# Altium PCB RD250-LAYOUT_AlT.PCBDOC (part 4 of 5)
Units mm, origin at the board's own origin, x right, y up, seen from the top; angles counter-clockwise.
Board outline 318.5 x 135 mm, 6 copper layers (TOP, Mid-Layer 1, Mid-Layer 2, Mid-Layer 3, Mid-Layer 4, BOTTOM), stack 1.422 mm thick; 550 components, 251 nets, 1350 pads, 626 vias.
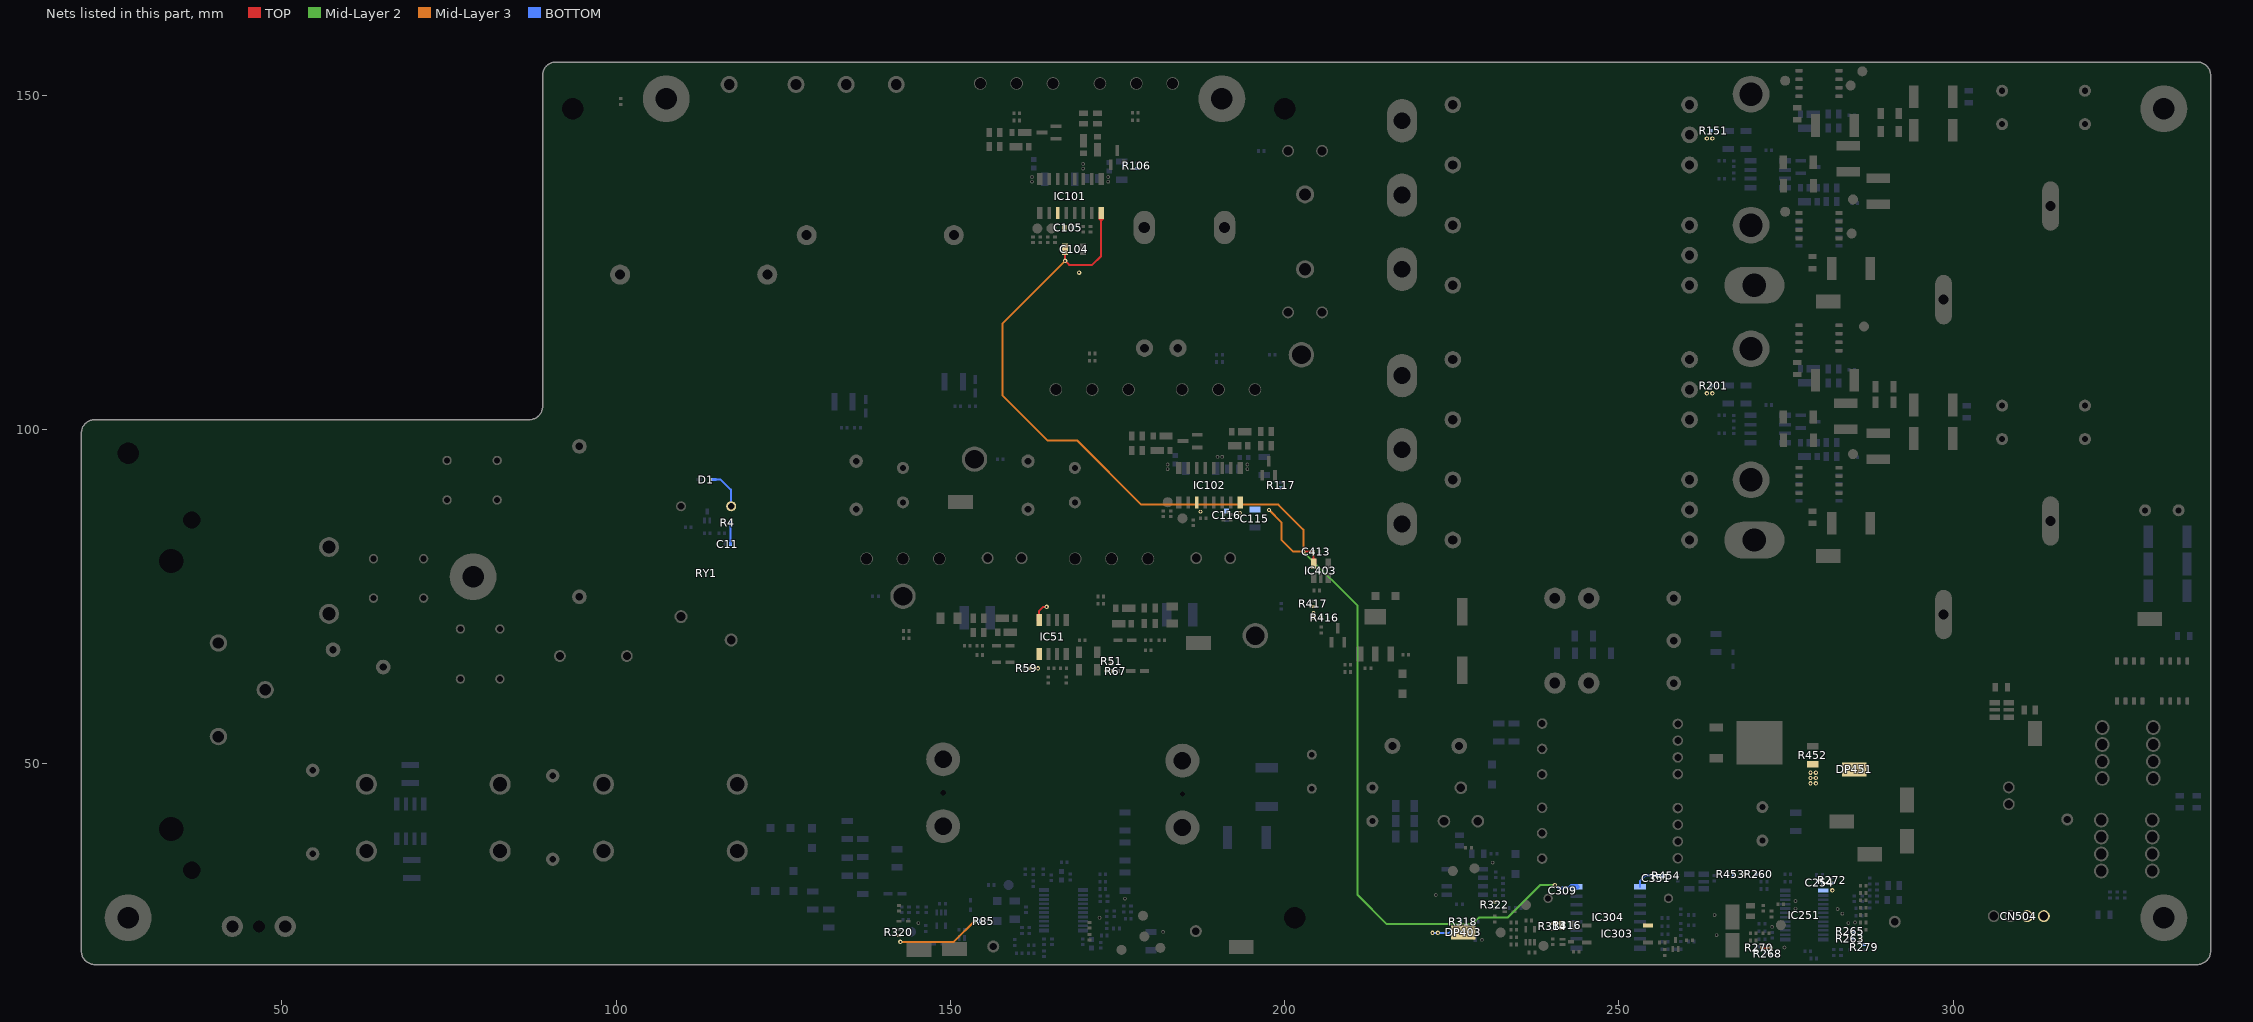
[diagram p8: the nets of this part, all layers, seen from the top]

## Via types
v1: diameter 0.65, hole 0.3, TOP to BOTTOM, 626 vias

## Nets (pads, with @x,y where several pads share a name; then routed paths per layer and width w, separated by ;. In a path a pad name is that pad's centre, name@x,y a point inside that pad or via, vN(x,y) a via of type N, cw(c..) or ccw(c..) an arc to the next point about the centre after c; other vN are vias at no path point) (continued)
VCC5R0_1: C104.2 C105.2 C115.2 C116.2 C309.2 C413.2 IC101.3 IC101.8 IC102.3 IC102.8 IC304.16 IC403.5 pad.@187.4,87.75 pad.@193.3,87.55 | length 199.5
  TOP w0.3: C104.2@167.15,126.61 v1(167.15,125.25) 167.75,124.65 171.2,124.65 172.533,125.983 IC101.8@172.533,131.659 ; v1(202.8,81.75) C413.2@204.147,81.75 ; IC403.5@204.312,80.386 C413.2@204.312,81.569
  TOP w0.425: C413.2@204.312,81.569 C413.2@204.312,81.75
  TOP w0.45: C413.2@204.147,81.75 204.312,81.75 C413.2@204.325,81.75
  TOP w0.824: IC101.8@172.533,131.659 IC101.8@172.533,132.392
  TOP w0.825: IC403.5@204.312,79.975 IC403.5@204.312,80.386
  TOP w0.92: C104.2@167.15,126.61 C104.2@167.15,127
  Mid-Layer 2 w0.3: v1(202.8,81.75) 210.9,73.65 210.9,30.4 215.25,26.05 228.1,26.05 229.042,26.992 cw(c229.183,26.85) 229.183,27.05 233.4,27.05 238.25,31.9 v1(240.4,31.9)
  Mid-Layer 3 w0.3: v1(167.15,125.25) 157.75,115.85 157.75,105.15 164.55,98.35 169,98.35 178.55,88.8 199.05,88.8 202.8,85.05 v1(202.8,81.75) 201.3,81.75 199.5,83.55 199.5,86.15 v1(197.65,88)
  BOTTOM w0.3: v1(240.4,31.9) 240.825,31.475 C309.2@241.372,31.475 ; C309.2@241.55,31.475 242.143,31.475 242.3,31.632 IC304.16@242.96,31.632
  BOTTOM w0.45: C309.2@241.372,31.475 C309.2@241.55,31.475
  BOTTOM w0.825: IC304.16@242.96,31.632 IC304.16@243.68,31.632
VCC5R0_2: C351.2 IC304.1 R454.2 | length 4.7
  BOTTOM w0.3: IC304.1@253.12,31.632 253.12,32.47 253.95,33.3 C351.2@255.431,33.3 ; C351.2@255.769,33.3 R454.2@256.497,33.3
  BOTTOM w0.4: C351.2@255.431,33.3 C351.2@255.769,33.3
  BOTTOM w0.45: R454.2@256.497,33.3 R454.2@256.675,33.3
VCC12R0_1: C11.2 D1.C DP403.1 IC51.1 IC51.8 R4.1 R51.1 R59.2 R67.2 R85.1 R106.1 R117.1 R314.2 R316.2 R318.2 R320.2 R322.2 R416.1 R417.1 RY1.4 | length 31.7
  TOP w0.3: R59.2@162.003,64.3 v1(163.1,64.3) ; IC51.8@163.257,72.043 163.257,72.907 163.85,73.5 v1(164.4,73.5) ; R314.2@240.278,26.125 R316.2@241.168,26.125
  TOP w0.45: R59.2@161.825,64.3 R59.2@162.003,64.3 ; R314.2@240.1,26.125 R314.2@240.278,26.125
  TOP w0.53: R316.2@241.168,26.125 R316.2@241.6,26.125
  TOP w0.825: IC51.8@163.257,71.557 IC51.8@163.257,72.043
  Mid-Layer 3 w0.3: v1(142.5,23.4) 150.417,23.4 ccw(c150.417,23.6) 150.559,23.459 v1(153.6,26.5)
  BOTTOM w0.3: D1.C@114.887,92.55 115.529,92.55 cw(c115.529,92.35) 115.671,92.491 117.141,91.021 cw(c117,90.879) 117.2,90.879 RY1.4@117.2,88.55 ; C11.2@117.125,83.087 R4.1@117.125,85.913 ; v1(222.1,24.75) v1(222.9,24.75) 224.625,24.75 R318.2@226.275,26.4
  BOTTOM w0.4: D1.C@114.5,92.55 D1.C@114.887,92.55
  BOTTOM w0.45: C11.2@117.125,82.9 C11.2@117.125,83.087 ; R4.1@117.125,85.913 R4.1@117.125,86.1
  other v1: 173.3,63.9 204.3,71.85 204.3,72.55 169.25,123.5
VCC12R0_2: CN504.1 CN504.2 DP451.1 IC303.6 pad.@268.8,33.5 R151.1 R201.1 R260.1 R452.2 R453.1
  other v1: 278.65,47.1 279.45,47.1 278.65,47.9 279.45,47.9 278.65,48.7 279.45,48.7 263.15,105.45 263.95,105.45 263.15,143.55 263.95,143.55
VREF_PSFB: C254.2 IC251.1 R263.2 R265.2 R268.2 R270.2 R272.2 R279.2 | length 1.3
  TOP w0.3: R270.2@271.553,22.5 v1(272.7,22.5)
  TOP w0.45: R270.2@271.375,22.5 R270.2@271.553,22.5
  other v1: 286.1,23.85 281.9,31.1
pads on no net: C51. C52. cam1. cam4. cam6. cam9. cam10. cam12. CN1. CN2.2 CN102.1 CN105.1 D104.NC D107.NC D113.NC D116.NC D405.NC IC1.1 IC1.4 IC1.5 IC1.8 IC101.7 IC101.12 IC101.13 IC102.7 IC102.12 IC102.13 IC151.1 IC151.8 IC201.1 IC201.8 IC251.16 IC304.7 IC304.10 IC403.4 IC451.4 T101.4 T101.6 T101.7 T151.1 T151.3 T151.4 T151.6 T151.7 T151.8 T151.9 T151.10 T151.11 T151.12 T201.1 T201.3 T201.4 T201.6 T201.7 T201.8 T201.9 T201.10 T201.11 T201.12 T401.2 T401.7 T401.10 T401.11 T401.14

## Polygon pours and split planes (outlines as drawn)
no net on Top Overlay "TOPOVERLAY378" (solid, pour order 0): 281.96,71.505 282.325,72.709 282.827,72.709 283.192,71.505 282.839,71.505 282.774,71.728 282.378,71.728 282.313,71.505
no net on Top Overlay "TOPOVERLAY377" (solid, pour order 0): 119 vertices, not listed, extent 280.833,71.505 281.873,72.709
no net on Top Overlay "TOPOVERLAY376" (solid, pour order 0): 145 vertices, not listed, extent 276.2,71.483 277.341,72.73
SIG1 on TOP "TOP127" (solid, pour order 372): 29 vertices, not listed, extent 52.1,45.209 64.395,74.2
VCC12R0_1 on TOP "TOP126" (solid, pour order 371): 142.1,22.9 cw(c142.1,23.05) 141.95,23.05 141.95,24.45 cw(c142.1,24.45) 142.1,24.6 142.65,24.6 cw(c142.65,24.45) 142.8,24.45 142.8,23.05 cw(c142.65,23.05) 142.65,22.9
SIG007123 on TOP "TOP125" (solid, pour order 370): 143.5,25.9 cw(c143.5,26.05) 143.35,26.05 143.35,26.55 cw(c143.5,26.55) 143.5,26.7 145.35,26.7 cw(c145.35,26.55) 145.5,26.55 145.5,26.05 cw(c145.35,26.05) 145.35,25.9
VCC12R0_1 on TOP "TOP124" (solid, pour order 369): 50 vertices, not listed, extent 226.248,24.348 240.325,30.7
SIG007124 on TOP "TOP123" (solid, pour order 368): 21 vertices, not listed, extent 237.15,24.785 240.324,25.75
SIG007127 on TOP "TOP122" (solid, pour order 367): 17 vertices, not listed, extent 231.15,27 233.05,28.7
SIG00797 on TOP "TOP121" (solid, pour order 366): 22 vertices, not listed, extent 234.2,24.8 236.85,29.65
SIG007112 on TOP "TOP120" (solid, pour order 365): 30 vertices, not listed, extent 229.284,20.75 239.45,23.916
PN on TOP "TOP119" (solid, pour order 364): 239.95,20.5 cw(c239.95,20.65) 239.8,20.65 239.8,23.05 cw(c239.95,23.05) 239.95,23.2 241.888,23.2 cw(c241.888,23.05) 241.994,23.156 242.95,22.2 243.25,22.2 cw(c243.25,22.05) 243.4,22.05 243.4,20.65 cw(c243.25,20.65) 243.25,20.5
SIG00234 on TOP "TOP118" (solid, pour order 363): 31 vertices, not listed, extent 149.985,22.263 165.964,27.37
SIG00233 on TOP "TOP117" (solid, pour order 362): 31 vertices, not listed, extent 144.954,21.854 165.964,30.17
SIG00839 on TOP "TOP116" (solid, pour order 361): 53 vertices, not listed, extent 207.676,65.977 214.675,75.748
SIG00839 on TOP "TOP115" (solid, pour order 360): 23 vertices, not listed, extent 212.684,64.109 214.05,66.973
SIGN267 on TOP "TOP114" (solid, pour order 359): 24 vertices, not listed, extent 143.601,69.675 149.11,72.383
SIG00447 on TOP "TOP113" (solid, pour order 358): 24 vertices, not listed, extent 266.25,127.1 281.2,137.5
SIG115 on TOP "TOP112" (solid, pour order 357): 24 vertices, not listed, extent 266.25,89 281.2,99.4
SIGN267 on TOP "TOP111" (solid, pour order 356): 36 vertices, not listed, extent 147.51,80.971 152.295,88.722
SIGN266 on TOP "TOP110" (solid, pour order 355): 51 vertices, not listed, extent 172.701,67.054 188.15,81.359
SIG199 on TOP "TOP109" (solid, pour order 354): 27 vertices, not listed, extent 80.144,44.471 100.612,62.805
SIG200 on TOP "TOP108" (solid, pour order 353): 80.875,35.202 cw(c82.643,36.97) 84.411,38.738 84.899,38.25 95.857,38.25 96.345,38.738 cw(c98.113,36.97) 99.881,35.202 98.661,33.982 cw(c96.893,35.75) 96.893,33.25 83.863,33.25 cw(c83.863,35.75) 82.095,33.982
VCC12R0_1 on TOP "TOP107" (solid, pour order 352): 32 vertices, not listed, extent 221.986,23.75 227.746,25.85
LGND on TOP "TOP106" (solid, pour order 351): 286.85,24.9 cw(c286.85,25.05) 286.7,25.05 286.7,31.95 cw(c286.85,31.95) 286.85,32.1 287.759,32.1 cw(c287.759,31.95) 287.9,32 292.497,27.403 cw(c292.391,27.297) 292.541,27.297 292.541,25.548 cw(c292.391,25.548) 292.497,25.442 291.999,24.944 cw(c291.893,25.05) 291.893,24.9
PFC_OUT on TOP "TOP105" (solid, pour order 350): 190.74,79.35 cw(c190.74,79.5) 190.59,79.5 190.59,81.7 cw(c190.74,81.7) 190.74,81.85 192.94,81.85 cw(c192.94,81.7) 193.09,81.7 193.09,79.5 cw(c192.94,79.5) 192.94,79.35
PFC_OUT on TOP "TOP104" (solid, pour order 349): 159.54,79.35 cw(c159.54,79.5) 159.39,79.5 159.39,81.7 cw(c159.54,81.7) 159.54,81.85 161.74,81.85 cw(c161.74,81.7) 161.89,81.7 161.89,79.5 cw(c161.74,79.5) 161.74,79.35
SIG11 on TOP "TOP103" (solid, pour order 348): 185.66,79.35 cw(c185.66,79.5) 185.51,79.5 185.51,81.7 cw(c185.66,81.7) 185.66,81.85 187.86,81.85 cw(c187.86,81.7) 188.01,81.7 188.01,79.5 cw(c187.86,79.5) 187.86,79.35
SIG12 on TOP "TOP102" (solid, pour order 347): 154.46,79.35 cw(c154.46,79.5) 154.31,79.5 154.31,81.7 cw(c154.46,81.7) 154.46,81.85 156.66,81.85 cw(c156.66,81.7) 156.81,81.7 156.81,79.5 cw(c156.66,79.5) 156.66,79.35
PN on TOP "TOP101" (solid, pour order 346): 167.56,79.35 cw(c167.56,79.5) 167.41,79.5 167.41,81.7 cw(c167.56,81.7) 167.56,81.85 169.76,81.85 cw(c169.76,81.7) 169.91,81.7 169.91,79.5 cw(c169.76,79.5) 169.76,79.35
PN on TOP "TOP100" (solid, pour order 345): 136.35,79.35 cw(c136.35,79.5) 136.2,79.5 136.2,81.7 cw(c136.35,81.7) 136.35,81.85 138.55,81.85 cw(c138.55,81.7) 138.7,81.7 138.7,79.5 cw(c138.55,79.5) 138.55,79.35
SIG22 on TOP "TOP99" (solid, pour order 344): 141.79,79.35 cw(c141.79,79.5) 141.64,79.5 141.64,81.7 cw(c141.79,81.7) 141.79,81.85 143.99,81.85 cw(c143.99,81.7) 144.14,81.7 144.14,79.5 cw(c143.99,79.5) 143.99,79.35
PN on TOP "TOP98" (solid, pour order 343): 140.7,150.15 cw(c140.7,150.3) 140.55,150.3 140.55,153 cw(c140.7,153) 140.7,153.15 143.1,153.15 cw(c143.1,153) 143.25,153 143.25,150.3 cw(c143.1,150.3) 143.1,150.15
PN on TOP "TOP97" (solid, pour order 342): 21 vertices, not listed, extent 230.6,21.5 236.9,26.6
SIG6 on TOP "TOP96" (solid, pour order 341): 42 vertices, not listed, extent 90.1,34.47 136.7,154.146
SIG0012 on TOP "TOP95" (solid, pour order 340): 26 vertices, not listed, extent 98.303,45.275 119.845,69.532
SIG2 on TOP "TOP94" (solid, pour order 339): 23 vertices, not listed, extent 38,34.032 64.2,55.8
SIGN266 on TOP "TOP93" (solid, pour order 338): 178.44,79.35 cw(c178.44,79.5) 178.29,79.5 178.29,81.7 cw(c178.44,81.7) 178.44,81.85 180.64,81.85 cw(c180.64,81.7) 180.79,81.7 180.79,79.5 cw(c180.64,79.5) 180.64,79.35
SIG18 on TOP "TOP92" (solid, pour order 337): 173,79.35 cw(c173,79.5) 172.85,79.5 172.85,81.7 cw(c173,81.7) 173,81.85 175.2,81.85 cw(c175.2,81.7) 175.35,81.7 175.35,79.5 cw(c175.2,79.5) 175.2,79.35
CONN004 on TOP "TOP91" (solid, pour order 336): 297.95,97 cw(c297.95,97.15) 297.8,97.15 297.8,105.3 cw(c297.95,105.3) 297.95,105.45 300.7,105.45 cw(c300.7,105.3) 300.85,105.3 300.85,97.15 cw(c300.7,97.15) 300.7,97
CONN004 on TOP "TOP90" (solid, pour order 335): 298,143.1 cw(c298,143.25) 297.85,143.25 297.85,151.4 cw(c298,151.4) 298,151.55 300.7,151.55 cw(c300.7,151.4) 300.85,151.4 300.85,143.25 cw(c300.7,143.25) 300.7,143.1
LGND on TOP "TOP89" (solid, pour order 334): 110 vertices, not listed, extent 282.15,69.825 337.9,154.45
SIG00852 on TOP "TOP88" (solid, pour order 333): 23 vertices, not listed, extent 267.6,41.8 279.9,60.4
SIG00345 on TOP "TOP87" (solid, pour order 332): 182.25,93.35 cw(c182.25,93.5) 182.1,93.5 182.1,95 cw(c182.25,95) 182.25,95.15 184.45,95.15 cw(c184.45,95) 184.6,95 184.6,93.5 cw(c184.45,93.5) 184.45,93.35
SIG00858 on TOP "TOP86" (solid, pour order 331): 30 vertices, not listed, extent 204.166,74 206.9,78.236
CONN002 on TOP "TOP85" (solid, pour order 330): 164.66,104.85 cw(c164.66,105) 164.51,105 164.51,107.2 cw(c164.66,107.2) 164.66,107.35 166.86,107.35 cw(c166.86,107.2) 167.01,107.2 167.01,105 cw(c166.86,105) 166.86,104.85
SIG00343 on TOP "TOP84" (solid, pour order 329): 170.1,104.85 cw(c170.1,105) 169.95,105 169.95,107.2 cw(c170.1,107.2) 170.1,107.35 172.3,107.35 cw(c172.3,107.2) 172.45,107.2 172.45,105 cw(c172.3,105) 172.3,104.85
SIG00351 on TOP "TOP83" (solid, pour order 328): 175.54,104.85 cw(c175.54,105) 175.39,105 175.39,107.2 cw(c175.54,107.2) 175.54,107.35 177.74,107.35 cw(c177.74,107.2) 177.89,107.2 177.89,105 cw(c177.74,105) 177.74,104.85
SIG00352 on TOP "TOP82" (solid, pour order 327): 194.44,104.85 cw(c194.44,105) 194.29,105 194.29,107.2 cw(c194.44,107.2) 194.44,107.35 196.64,107.35 cw(c196.64,107.2) 196.79,107.2 196.79,105 cw(c196.64,105) 196.64,104.85
CONN002 on TOP "TOP81" (solid, pour order 326): 189,104.85 cw(c189,105) 188.85,105 188.85,107.2 cw(c189,107.2) 189,107.35 191.2,107.35 cw(c191.2,107.2) 191.35,107.2 191.35,105 cw(c191.2,105) 191.2,104.85
PN on TOP "TOP80" (solid, pour order 325): 183.56,104.85 cw(c183.56,105) 183.41,105 183.41,107.2 cw(c183.56,107.2) 183.56,107.35 185.76,107.35 cw(c185.76,107.2) 185.91,107.2 185.91,105 cw(c185.76,105) 185.76,104.85
SIG8 on TOP "TOP79" (solid, pour order 324): 125.7,150.15 cw(c125.7,150.3) 125.55,150.3 125.55,153 cw(c125.7,153) 125.7,153.15 128.1,153.15 cw(c128.1,153) 128.25,153 128.25,150.3 cw(c128.1,150.3) 128.1,150.15
PFC_OUT on TOP "TOP78" (solid, pour order 323): 115.7,150.15 cw(c115.7,150.3) 115.55,150.3 115.55,153 cw(c115.7,153) 115.7,153.15 118.1,153.15 cw(c118.1,153) 118.25,153 118.25,150.3 cw(c118.1,150.3) 118.1,150.15
SIGN267 on TOP "TOP77" (solid, pour order 322): 147.24,79.35 cw(c147.24,79.5) 147.09,79.5 147.09,81.7 cw(c147.24,81.7) 147.24,81.85 149.44,81.85 cw(c149.44,81.7) 149.59,81.7 149.59,79.5 cw(c149.44,79.5) 149.44,79.35
SIG00343 on TOP "TOP76" (solid, pour order 321): 158.8,150.55 cw(c158.8,150.7) 158.65,150.7 158.65,152.9 cw(c158.8,152.9) 158.8,153.05 161,153.05 cw(c161,152.9) 161.15,152.9 161.15,150.7 cw(c161,150.7) 161,150.55
SIG00356 on TOP "TOP75" (solid, pour order 320): 153.36,150.55 cw(c153.36,150.7) 153.21,150.7 153.21,152.9 cw(c153.36,152.9) 153.36,153.05 155.56,153.05 cw(c155.56,152.9) 155.71,152.9 155.71,150.7 cw(c155.56,150.7) 155.56,150.55
PN on TOP "TOP74" (solid, pour order 319): 182.14,150.55 cw(c182.14,150.7) 181.99,150.7 181.99,152.9 cw(c182.14,152.9) 182.14,153.05 184.34,153.05 cw(c184.34,152.9) 184.49,152.9 184.49,150.7 cw(c184.34,150.7) 184.34,150.55
SIG00362 on TOP "TOP73" (solid, pour order 318): 176.7,150.55 cw(c176.7,150.7) 176.55,150.7 176.55,152.9 cw(c176.7,152.9) 176.7,153.05 178.9,153.05 cw(c178.9,152.9) 179.05,152.9 179.05,150.7 cw(c178.9,150.7) 178.9,150.55
SIG00342 on TOP "TOP72" (solid, pour order 317): 171.26,150.55 cw(c171.26,150.7) 171.11,150.7 171.11,152.9 cw(c171.26,152.9) 171.26,153.05 173.46,153.05 cw(c173.46,152.9) 173.61,152.9 173.61,150.7 cw(c173.46,150.7) 173.46,150.55
SIG00362 on TOP "TOP71" (solid, pour order 316): 164.24,150.55 cw(c164.24,150.7) 164.09,150.7 164.09,152.9 cw(c164.24,152.9) 164.24,153.05 166.44,153.05 cw(c166.44,152.9) 166.59,152.9 166.59,150.7 cw(c166.44,150.7) 166.44,150.55
LGND on TOP "TOP70" (solid, pour order 315): 315.15,32.1 cw(c315.15,32.25) 315,32.25 315,43.7 cw(c315.15,43.7) 315.15,43.85 337.8,43.85 cw(c337.8,43.7) 337.95,43.7 337.95,32.25 cw(c337.8,32.25) 337.8,32.1
SIG00461 on TOP "TOP69" (solid, pour order 314): 24 vertices, not listed, extent 278.5,97 294.8,107.35
LGND on TOP "TOP68" (solid, pour order 313): 28 vertices, not listed, extent 282.35,84.3 290.7,96.3
SIG00445 on TOP "TOP67" (solid, pour order 312): 29 vertices, not listed, extent 265,100.9 281.2,116.1
SIG00457 on TOP "TOP66" (solid, pour order 311): 29 vertices, not listed, extent 265,139 281.2,154.2
SIG00333 on TOP "TOP65" (solid, pour order 310): 17 vertices, not listed, extent 169.35,137.233 172.55,142.4
SIG00362 on TOP "TOP64" (solid, pour order 309): 19 vertices, not listed, extent 165.05,137.233 166.5,143.75
SIG00339 on TOP "TOP63" (solid, pour order 308): 164.5,138.6 161.344,141.756 cw(c161.45,141.862) 161.3,141.862 161.3,144.838 cw(c161.45,144.838) 161.344,144.944 161.603,145.203 cw(c161.709,145.097) 161.709,145.247 164.338,145.247 cw(c164.338,145.097) 164.488,145.097 164.488,139.912 165.006,139.394 cw(c164.9,139.288) 165.05,139.288 165.05,137.507 cw(c164.775,137.507) 164.5,137.507
SIG00334 on TOP "TOP62" (solid, pour order 307): 161.95,136.6 cw(c161.95,136.75) 161.8,136.75 161.8,138.3 cw(c161.95,138.3) 161.95,138.45 163.65,138.45 cw(c163.65,138.3) 163.8,138.3 163.8,136.75 cw(c163.65,136.75) 163.65,136.6
SIG00347 on TOP "TOP61" (solid, pour order 306): 26 vertices, not listed, extent 181.25,93.9 185.85,99.6
CONN002 on TOP "TOP60" (solid, pour order 305): 186.57,95.18 185.894,95.856 cw(c186,95.962) 185.85,95.962 185.85,97.5 cw(c186,97.5) 186,97.65 187.35,97.65 cw(c187.35,97.5) 187.5,97.5 187.5,97.042 cw(c187.35,97.042) 187.456,96.936 187.12,96.6 187.12,94.258 cw(c186.845,94.258) 186.57,94.258
PN on TOP "TOP59" (solid, pour order 304): 33 vertices, not listed, extent 187.85,85.35 192.3,90.05
SIG00361 on TOP "TOP58" (solid, pour order 303): 26 vertices, not listed, extent 183.9,85.95 187.6,89.8
VCC5R0_1 on TOP "TOP57" (solid, pour order 302): 192.95,87.25 cw(c192.95,87.4) 192.8,87.4 192.8,88.188 cw(c192.95,88.188) 192.844,88.294 193,88.45 193,89.4 cw(c193.15,89.4) 193.15,89.55 193.6,89.55 cw(c193.6,89.4) 193.75,89.4 193.75,87.4 cw(c193.6,87.4) 193.6,87.25
SIG00360 on TOP "TOP56" (solid, pour order 301): 181.7,87.65 cw(c181.7,87.8) 181.55,87.8 181.55,89.388 cw(c181.7,89.388) 181.594,89.494 182.106,90.006 cw(c182.212,89.9) 182.212,90.05 184.45,90.05 cw(c184.45,89.9) 184.6,89.9 184.6,88.312 cw(c184.45,88.312) 184.556,88.206 184.044,87.694 cw(c183.938,87.8) 183.938,87.65
VCC5R0_1 on TOP "TOP55" (solid, pour order 300): 187.312,87.45 cw(c187.312,87.6) 187.206,87.494 186.614,88.086 cw(c186.72,88.192) 186.57,88.192 186.57,89.5 cw(c186.72,89.5) 186.72,89.65 186.97,89.65 cw(c186.97,89.5) 187.12,89.5 187.12,88.53 187.706,87.944 cw(c187.6,87.838) 187.75,87.838 187.75,87.6 cw(c187.6,87.6) 187.6,87.45
SIG00346 on TOP "TOP54" (solid, pour order 299): 34 vertices, not listed, extent 191.55,94 197.754,99.925
PN on TOP "TOP53" (solid, pour order 298): 18 vertices, not listed, extent 192.9,92.4 196.8,95.15
SIG00353 on TOP "TOP52" (solid, pour order 297): 190.38,95.12 189.694,95.806 cw(c189.8,95.912) 189.65,95.912 189.65,96.1 cw(c189.8,96.1) 189.8,96.25 190.78,96.25 cw(c190.78,96.1) 190.93,96.1 190.93,94.258 cw(c190.655,94.258) 190.38,94.258
LGND on TOP "TOP51" (solid, pour order 296): 28 vertices, not listed, extent 282.35,122.4 290.7,134.4
SIG00458 on TOP "TOP50" (solid, pour order 295): 23 vertices, not listed, extent 278.5,135.5 294.85,151.6
PN on TOP "TOP49" (solid, pour order 294): 33 vertices, not listed, extent 167.05,125.15 171.25,133.3
SIG00858 on TOP "TOP48" (solid, pour order 293): 204.15,74.15 cw(c204.15,74.3) 204,74.3 204,75.15 203.944,75.206 cw(c204.05,75.312) 203.9,75.312 203.9,78.45 cw(c204.05,78.45) 204.05,78.6 204.6,78.6 cw(c204.6,78.45) 204.75,78.45 204.75,76.962 cw(c204.6,76.962) 204.706,76.856 204.6,76.75 204.6,74.3 cw(c204.45,74.3) 204.45,74.15
VCC12R0_1 on TOP "TOP47" (solid, pour order 292): 204.2,71.55 cw(c204.2,71.8) 203.95,71.8 203.95,73.6 cw(c204.1,73.6) 204.1,73.75 204.425,73.75 cw(c204.425,73.6) 204.575,73.6 204.575,72.775 204.85,72.5 205.5,72.5 cw(c205.5,72.25) 205.75,72.25 205.75,71.8 cw(c205.5,71.8) 205.5,71.55
PN on TOP "TOP46" (solid, pour order 291): 163.862,126.8 cw(c163.862,126.95) 163.756,126.844 163.194,127.406 cw(c163.3,127.512) 163.15,127.512 163.15,128.05 cw(c163.3,128.05) 163.3,128.2 164.7,128.2 cw(c164.7,128.05) 164.85,128.05 164.85,126.95 cw(c164.7,126.95) 164.7,126.8
PN on TOP "TOP45" (solid, pour order 290): 172.25,136.6 cw(c172.25,136.75) 172.1,136.75 172.1,138.25 cw(c172.25,138.25) 172.25,138.4 173,138.4 173.7,139.1 173.7,140.35 cw(c173.85,140.35) 173.85,140.5 174.15,140.5 cw(c174.15,140.35) 174.3,140.35 174.3,138.262 cw(c174.15,138.262) 174.256,138.156 173.95,137.85 173.95,136.75 cw(c173.8,136.75) 173.8,136.6
SIG00336 on TOP "TOP44" (solid, pour order 289): 169.58,139.95 cw(c169.73,139.95) 169.73,140.1 169.98,140.1 cw(c169.98,139.95) 170.13,139.95 170.13,137.507 cw(c169.855,137.507) 169.58,137.507
SIG00359 on TOP "TOP43" (solid, pour order 288): 164.4,128.6 cw(c164.4,128.75) 164.25,128.75 164.25,131.238 cw(c164.4,131.238) 164.294,131.344 164.5,131.55 164.5,133.15 cw(c164.65,133.15) 164.65,133.3 164.9,133.3 cw(c164.9,133.15) 165.05,133.15 165.05,131.4 165.906,130.544 cw(c165.8,130.438) 165.95,130.438 165.95,128.75 cw(c165.8,128.75) 165.8,128.6
SIG00358 on TOP "TOP42" (solid, pour order 287): 162.2,128.6 cw(c162.2,128.75) 162.05,128.75 162.05,130.588 cw(c162.2,130.588) 162.094,130.694 162.95,131.55 162.95,133.15 cw(c163.1,133.15) 163.1,133.3 163.65,133.3 cw(c163.65,133.15) 163.8,133.15 163.8,128.75 cw(c163.65,128.75) 163.65,128.6
VCC5R0_1 on TOP "TOP41" (solid, pour order 286): 21 vertices, not listed, extent 165.75,126.15 167.6,133.3
SIG00450 on TOP "TOP40" (solid, pour order 285): 19 vertices, not listed, extent 282.35,94.08 285.8,97.3
VCC12R0_1 on TOP "TOP39" (solid, pour order 284): 22 vertices, not listed, extent 162.831,63.981 163.67,66.854
LGND on TOP "TOP38" (solid, pour order 283): 22 vertices, not listed, extent 257.85,35.7 275.5,42.1
LGND on TOP "TOP37" (solid, pour order 282): 24 vertices, not listed, extent 254.75,21.15 260.2,22.8
VCC12R0_2 on TOP "TOP36" (solid, pour order 281): 75 vertices, not listed, extent 254.026,25.57 286.246,50.4
SIG00439 on TOP "TOP35" (solid, pour order 280): 19 vertices, not listed, extent 282.35,152.75 287.15,154.4
SIG100 on TOP "TOP34" (solid, pour order 279): 20 vertices, not listed, extent 176.102,72.7 179.4,73.9
SIG23 on TOP "TOP33" (solid, pour order 278): 180.2,73.3 cw(c180.6,73.3) 181,73.3 181,71 cw(c180.6,71) 180.2,71
SIG23 on TOP "TOP32" (solid, pour order 277): 21 vertices, not listed, extent 180.186,70.44 183.783,71.61
SIG101 on TOP "TOP31" (solid, pour order 276): 21 vertices, not listed, extent 176.65,70.4 179.4,71.6
SIG106 on TOP "TOP30" (solid, pour order 275): 20 vertices, not listed, extent 154.7,71.25 158.298,72.35
SIG27 on TOP "TOP29" (solid, pour order 274): 21 vertices, not listed, extent 150.492,71.215 153.75,72.385
SIGN267 on TOP "TOP28" (solid, pour order 273): 17 vertices, not listed, extent 147.428,71 149.252,80.999
SIG105 on TOP "TOP27" (solid, pour order 272): 21 vertices, not listed, extent 154.7,69.15 157.45,70.25
SIG27 on TOP "TOP26" (solid, pour order 271): 153,71.8 cw(c153.4,71.8) 153.8,71.8 153.8,69.7 cw(c153.4,69.7) 153,69.7
SIG102 on TOP "TOP25" (solid, pour order 270): 56 vertices, not listed, extent 166.943,68.226 175.7,73.699
SIG30 on TOP "TOP24" (solid, pour order 269): 40 vertices, not listed, extent 158.4,67.598 164.95,72.25
SIG104 on TOP "TOP23" (solid, pour order 268): 34 vertices, not listed, extent 165.685,66.242 172.41,71.807
VCC12R0_1 on TOP "TOP22" (solid, pour order 267): 173.162,63.6 cw(c173.162,63.75) 173.056,63.644 172.944,63.756 cw(c173.05,63.862) 172.9,63.862 172.9,64.338 cw(c173.05,64.338) 172.944,64.444 173.656,65.156 cw(c173.762,65.05) 173.762,65.2 174.35,65.2 cw(c174.35,65.05) 174.5,65.05 174.5,63.75 cw(c174.35,63.75) 174.35,63.6
PN on TOP "TOP21" (solid, pour order 266): 29 vertices, not listed, extent 165.25,63.25 169.7,68.8
SIG104 on TOP "TOP20" (solid, pour order 265): 17 vertices, not listed, extent 171.45,63.25 174.4,67.55
SIG00448 on TOP "TOP19" (solid, pour order 264): 24 vertices, not listed, extent 264.65,79.95 282.346,87.05
SIG00446 on TOP "TOP18" (solid, pour order 263): 24 vertices, not listed, extent 264.7,118 282.346,125.15
SIG00837 on TOP "TOP17" (solid, pour order 262): 262.912,47.15 cw(c262.912,47.3) 262.806,47.194 260.05,49.95 257.9,49.95 cw(c257.9,50.1) 257.75,50.1 257.75,54.3 cw(c257.9,54.3) 257.9,54.45 260.55,54.45 262.856,56.756 cw(c262.962,56.65) 262.962,56.8 265.55,56.8 cw(c265.55,56.65) 265.7,56.65 265.7,47.3 cw(c265.55,47.3) 265.55,47.15
SIG141 on TOP "TOP16" (solid, pour order 261): 37 vertices, not listed, extent 311.836,57.685 324.743,65.8
PN on TOP "TOP15" (solid, pour order 260): 19 vertices, not listed, extent 205.15,63.526 209.25,69.85
P48V on TOP "TOP14" (solid, pour order 259): 29 vertices, not listed, extent 307.912,44.85 337.95,63.7
CONN004 on TOP "TOP13" (solid, pour order 258): 33 vertices, not listed, extent 313.1,64.85 335.4,90.6
CONN004 on TOP "TOP12" (solid, pour order 257): 17 vertices, not listed, extent 313.25,129.55 321.45,137.5
SIG141 on TOP "TOP11" (solid, pour order 256): 329.55,64.85 cw(c329.55,65) 329.4,65 329.4,66.45 cw(c329.55,66.45) 329.55,66.6 331.35,66.6 cw(c331.35,66.45) 331.5,66.45 331.5,65 cw(c331.35,65) 331.35,64.85
SIG00839 on TOP "TOP10" (solid, pour order 255): 23 vertices, not listed, extent 206.198,70.9 214.675,73.15
SIG00862 on TOP "TOP9" (solid, pour order 254): 34 vertices, not listed, extent 209.65,63.526 212.249,66.973
SIG00860 on TOP "TOP8" (solid, pour order 253): 41 vertices, not listed, extent 215.35,65.977 227.347,75.748
SIG00862 on TOP "TOP7" (solid, pour order 252): 21 vertices, not listed, extent 206.79,65.975 211.748,68.409
LGND on TOP "TOP6" (solid, pour order 251): 19 vertices, not listed, extent 303.9,57.4 306.35,58.8
SIG00449 on TOP "TOP5" (solid, pour order 250): 19 vertices, not listed, extent 282.35,132.18 285.8,135.4
SIG00440 on TOP "TOP4" (solid, pour order 249): 19 vertices, not listed, extent 282.35,114.65 287.45,116.3
PN on TOP "TOP3" (solid, pour order 248): 222.262,61.95 cw(c222.262,62.1) 222.156,61.994 218.344,65.806 cw(c218.45,65.912) 218.3,65.912 218.3,66.588 cw(c218.45,66.588) 218.344,66.694 218.456,66.806 cw(c218.562,66.7) 218.562,66.85 224.938,66.85 cw(c224.938,66.7) 225.044,66.806 225.75,66.1 227.2,66.1 cw(c227.2,65.95) 227.35,65.95 227.35,62.1 cw(c227.2,62.1) 227.2,61.95
SIG00860 on TOP "TOP2" (solid, pour order 247): 17 vertices, not listed, extent 215.35,62.9 218.25,67.1
SIG00526 on TOP "TOP1" (solid, pour order 246): 272.35,24.4 cw(c272.35,24.55) 272.2,24.55 272.2,27.088 cw(c272.35,27.088) 272.244,27.194 272.356,27.306 cw(c272.462,27.2) 272.462,27.35 274.188,27.35 cw(c274.188,27.2) 274.294,27.306 275.006,26.594 cw(c274.9,26.488) 275.05,26.488 275.05,25.162 cw(c274.9,25.162) 275.006,25.056 274.394,24.444 cw(c274.288,24.55) 274.288,24.4
SIG200 on Mid-Layer 1 "MID1140" (solid, pour order 245): 80.221,39.018 cw(c80.315,39.052) 80.242,39.12 80.48,39.376 cw(c80.553,39.308) 80.587,39.402 83.026,38.505 cw(c82.992,38.411) 83.062,38.339 81.261,36.583 cw(c81.191,36.654) 81.097,36.62
SIG200 on Mid-Layer 1 "MID1139" (solid, pour order 244): 76.522,61.25 cw(c76.522,61.35) 76.427,61.318 76.069,62.393 cw(c76.164,62.425) 76.164,62.525 77.236,62.525 cw(c77.236,62.425) 77.331,62.393 76.973,61.318 cw(c76.878,61.35) 76.878,61.25
PN on Mid-Layer 1 "MID1138" (solid, pour order 243): 396 vertices, not listed, extent 100.475,20.55 243.4,153.85
PN on Mid-Layer 1 "MID1137" (solid, pour order 242): 24 vertices, not listed, extent 155.8,20.9 178.65,35.65
LGND on Mid-Layer 1 "MID1136" (solid, pour order 241): 131 vertices, not listed, extent 253.95,20.6 337.95,154.45
LGND on Mid-Layer 1 "MID1135" (solid, pour order 240): 32 vertices, not listed, extent 266,90.1 285.3,114.6
LGND on Mid-Layer 1 "MID1134" (solid, pour order 239): 32 vertices, not listed, extent 266,128.2 285.3,152.7
SIG00362 on Mid-Layer 1 "MID1133" (solid, pour order 238): 24 vertices, not listed, extent 155.8,136.55 166.6,153.05
CONN002 on Mid-Layer 1 "MID1132" (solid, pour order 237): 32 vertices, not listed, extent 164.65,93.35 187.3,107
PN on Mid-Layer 1 "MID1131" (solid, pour order 236): 184.691,83.9 cw(c184.691,84) 184.621,83.929 182.679,85.871 cw(c182.75,85.941) 182.65,85.941 182.65,90 cw(c182.75,90) 182.75,90.1 195.05,90.1 cw(c195.05,90) 195.15,90 195.15,84 cw(c195.05,84) 195.05,83.9
PN on Mid-Layer 1 "MID1130" (solid, pour order 235): 20 vertices, not listed, extent 162.9,126 174.25,133.3
LGND on Mid-Layer 1 "MID1129" (solid, pour order 234): 265.2,99.85 cw(c265.2,99.95) 265.1,99.95 265.1,102.35 cw(c265.2,102.35) 265.2,102.45 270.1,102.45 cw(c270.1,102.35) 270.2,102.35 270.2,99.95 cw(c270.1,99.95) 270.1,99.85
LGND on Mid-Layer 1 "MID1128" (solid, pour order 233): 265.2,137.95 cw(c265.2,138.05) 265.1,138.05 265.1,140.45 cw(c265.2,140.45) 265.2,140.55 270.1,140.55 cw(c270.1,140.45) 270.2,140.45 270.2,138.05 cw(c270.1,138.05) 270.1,137.95
PFC_OUT on Mid-Layer 2 "MID2158" (solid, pour order 232): 184.444,47.969 cw(c184.46,48.068) 184.39,48.139 187.062,50.788 cw(c187.132,50.717) 187.231,50.733 187.717,47.725 cw(c187.618,47.71) 187.689,47.639 187.561,47.511 cw(c187.49,47.582) 187.475,47.483
LGND on Mid-Layer 2 "MID2157" (solid, pour order 231): 308.224,43.107 cw(c308.248,43.204) 308.178,43.275 309.026,44.104 cw(c309.096,44.032) 309.193,44.057 309.436,43.105 cw(c309.339,43.08) 309.41,43.01 309.29,42.89 cw(c309.219,42.961) 309.195,42.864
P48V on Mid-Layer 2 "MID2156" (solid, pour order 230): 308.26,47.252 cw(c308.334,47.318) 308.31,47.415 309.195,47.636 cw(c309.219,47.539) 309.29,47.61 309.41,47.49 cw(c309.339,47.419) 309.436,47.395 309.196,46.434 cw(c309.099,46.458) 309.024,46.392
SIG0012 on Mid-Layer 2 "MID2155" (solid, pour order 229): 100.954,66.55 cw(c100.954,66.65) 100.863,66.691 101.399,67.891 cw(c101.49,67.85) 101.49,67.95 101.685,67.95 cw(c101.685,67.85) 101.776,67.891 102.312,66.691 cw(c102.221,66.65) 102.221,66.55
SIG0012 on Mid-Layer 2 "MID2154" (solid, pour order 228): 82.5,89.973 cw(c82.6,89.973) 82.639,90.065 83.314,89.776 cw(c83.275,89.684) 83.375,89.684 83.375,89.316 cw(c83.275,89.316) 83.314,89.224 82.639,88.935 cw(c82.6,89.027) 82.5,89.027
SIG2 on Mid-Layer 2 "MID2153" (solid, pour order 227): 63.717,63.333 cw(c63.787,63.404) 63.691,63.432 64.054,64.69 cw(c64.15,64.663) 64.22,64.735 65.402,63.594 cw(c65.333,63.522) 65.361,63.426 64.082,63.042 cw(c64.053,63.138) 63.983,63.067
SIG2 on Mid-Layer 2 "MID2152" (solid, pour order 226): 41.1,55.076 cw(c41.2,55.076) 41.25,55.163 42.6,54.379 cw(c42.55,54.292) 42.65,54.292 42.65,53.908 cw(c42.55,53.908) 42.6,53.821 41.25,53.037 cw(c41.2,53.124) 41.1,53.124
SIG2 on Mid-Layer 2 "MID2151" (solid, pour order 225): 40.308,51.95 cw(c40.308,52.05) 40.221,52 39.386,53.45 cw(c39.473,53.5) 39.473,53.6 41.527,53.6 cw(c41.527,53.5) 41.614,53.45 40.779,52 cw(c40.692,52.05) 40.692,51.95
SIG2 on Mid-Layer 2 "MID2150" (solid, pour order 224): 41.405,26.525 cw(c41.405,26.625) 41.32,26.678 42.296,28.253 cw(c42.381,28.2) 42.381,28.3 42.779,28.3 cw(c42.779,28.2) 42.864,28.253 43.842,26.678 cw(c43.757,26.625) 43.757,26.525
CONN002 on Mid-Layer 2 "MID2149" (solid, pour order 223): 65 vertices, not listed, extent 163.97,82.8 220,132.1
CONN004 on Mid-Layer 2 "MID2148" (solid, pour order 222): 68 vertices, not listed, extent 298.75,69.35 337.95,149.3
SIG00362 on Mid-Layer 2 "MID2147" (solid, pour order 221): 28 vertices, not listed, extent 163.59,127.6 184.1,153.55
VCC12R0_2 on Mid-Layer 2 "MID2146" (solid, pour order 220): 61 vertices, not listed, extent 255.95,46.4 280.1,144.15
SIG00440 on Mid-Layer 2 "MID2145" (solid, pour order 219): 21 vertices, not listed, extent 282.35,109.45 285.45,116.05
VREF_PSFB on Mid-Layer 2 "MID2144" (solid, pour order 218): 42 vertices, not listed, extent 272.475,22.275 286.191,31.191
SIG00449 on Mid-Layer 2 "MID2143" (solid, pour order 217): 282.45,127 cw(c282.45,127.1) 282.35,127.1 282.35,135 cw(c282.45,135) 282.45,135.1 285.05,135.1 cw(c285.05,135) 285.15,135 285.15,132.95 cw(c285.05,132.95) 285.05,132.85 284.05,132.85 ccw(c284.05,132.15) 284.05,131.45 285.05,131.45 cw(c285.05,131.35) 285.15,131.35 285.15,127.1 cw(c285.05,127.1) 285.05,127
SIG00439 on Mid-Layer 2 "MID2142" (solid, pour order 216): 22 vertices, not listed, extent 282.35,147.55 285.45,154.15
SIG00450 on Mid-Layer 2 "MID2141" (solid, pour order 215): 282.45,88.9 cw(c282.45,89) 282.35,89 282.35,96.9 cw(c282.45,96.9) 282.45,97 285.05,97 cw(c285.05,96.9) 285.15,96.9 285.15,94.35 cw(c285.05,94.35) 285.05,94.25 284.05,94.25 ccw(c284.05,93.55) 284.05,92.85 285.05,92.85 cw(c285.05,92.75) 285.15,92.75 285.15,89 cw(c285.05,89) 285.05,88.9
SIG193 on Mid-Layer 3 "MID3169" (solid, pour order 214): 38.841,66.709 cw(c38.911,66.78) 38.815,66.806 39.206,68.282 cw(c39.302,68.256) 39.373,68.327 40.727,66.973 cw(c40.656,66.902) 40.682,66.806 39.206,66.415 cw(c39.18,66.511) 39.109,66.441
SIG193 on Mid-Layer 3 "MID3168" (solid, pour order 213): 49.33,26.525 cw(c49.33,26.625) 49.245,26.678 50.221,28.253 cw(c50.306,28.2) 50.306,28.3 50.694,28.3 cw(c50.694,28.2) 50.779,28.253 51.755,26.678 cw(c51.67,26.625) 51.67,26.525
SIG00234 on Mid-Layer 3 "MID3167" (solid, pour order 212): 42 vertices, not listed, extent 164.25,26.793 166.55,61.086
SIG00233 on Mid-Layer 3 "MID3166" (solid, pour order 211): 30 vertices, not listed, extent 165.614,29.665 167.643,60.953
VCC12R0_1 on Mid-Layer 3 "MID3165" (solid, pour order 210): 186 vertices, not listed, extent 116.752,24.426 223.15,123.795
CONN002 on Mid-Layer 3 "MID3164" (solid, pour order 209): 65 vertices, not listed, extent 163.97,82.8 220,132.1
CONN004 on Mid-Layer 3 "MID3163" (solid, pour order 208): 87 vertices, not listed, extent 298.75,64.85 337.95,149.3
SIG00440 on Mid-Layer 3 "MID3162" (solid, pour order 207): 21 vertices, not listed, extent 282.35,109.45 285.45,116.05
SIG00449 on Mid-Layer 3 "MID3161" (solid, pour order 206): 282.45,127 cw(c282.45,127.1) 282.35,127.1 282.35,135 cw(c282.45,135) 282.45,135.1 285.05,135.1 cw(c285.05,135) 285.15,135 285.15,132.95 cw(c285.05,132.95) 285.05,132.85 284.05,132.85 ccw(c284.05,132.15) 284.05,131.45 285.05,131.45 cw(c285.05,131.35) 285.15,131.35 285.15,127.1 cw(c285.05,127.1) 285.05,127
SIG00439 on Mid-Layer 3 "MID3160" (solid, pour order 205): 22 vertices, not listed, extent 282.35,147.55 285.45,154.15
SIG00450 on Mid-Layer 3 "MID3159" (solid, pour order 204): 282.45,88.9 cw(c282.45,89) 282.35,89 282.35,96.9 cw(c282.45,96.9) 282.45,97 285.05,97 cw(c285.05,96.9) 285.15,96.9 285.15,94.35 cw(c285.05,94.35) 285.05,94.25 284.05,94.25 ccw(c284.05,93.55) 284.05,92.85 285.05,92.85 cw(c285.05,92.75) 285.15,92.75 285.15,89 cw(c285.05,89) 285.05,88.9
PN on Mid-Layer 4 "MID4180" (solid, pour order 203): 396 vertices, not listed, extent 100.475,20.55 243.4,153.85
PN on Mid-Layer 4 "MID4179" (solid, pour order 202): 24 vertices, not listed, extent 155.8,20.9 178.65,35.65
LGND on Mid-Layer 4 "MID4178" (solid, pour order 201): 131 vertices, not listed, extent 253.95,20.6 337.95,154.45
LGND on Mid-Layer 4 "MID4177" (solid, pour order 200): 265.2,137.95 cw(c265.2,138.05) 265.1,138.05 265.1,140.45 cw(c265.2,140.45) 265.2,140.55 270.1,140.55 cw(c270.1,140.45) 270.2,140.45 270.2,138.05 cw(c270.1,138.05) 270.1,137.95
LGND on Mid-Layer 4 "MID4176" (solid, pour order 199): 32 vertices, not listed, extent 266,128.2 285.3,152.7
LGND on Mid-Layer 4 "MID4175" (solid, pour order 198): 265.2,99.85 cw(c265.2,99.95) 265.1,99.95 265.1,102.35 cw(c265.2,102.35) 265.2,102.45 270.1,102.45 cw(c270.1,102.35) 270.2,102.35 270.2,99.95 cw(c270.1,99.95) 270.1,99.85
LGND on Mid-Layer 4 "MID4174" (solid, pour order 197): 32 vertices, not listed, extent 266,90.1 285.3,114.6
SIG00362 on Mid-Layer 4 "MID4173" (solid, pour order 196): 24 vertices, not listed, extent 155.8,136.55 166.6,153.05
PN on Mid-Layer 4 "MID4172" (solid, pour order 195): 20 vertices, not listed, extent 162.9,126 174.25,133.3
CONN002 on Mid-Layer 4 "MID4171" (solid, pour order 194): 32 vertices, not listed, extent 164.65,93.35 187.3,107
PN on Mid-Layer 4 "MID4170" (solid, pour order 193): 184.691,83.9 cw(c184.691,84) 184.621,83.929 182.679,85.871 cw(c182.75,85.941) 182.65,85.941 182.65,90 cw(c182.75,90) 182.75,90.1 195.05,90.1 cw(c195.05,90) 195.15,90 195.15,84 cw(c195.05,84) 195.05,83.9
PN on BOTTOM "BOTTOM371" (solid, pour order 192): 18 vertices, not listed, extent 228.7,24.15 231.6,26.7
SIG007125 on BOTTOM "BOTTOM370" (solid, pour order 191): 227.05,24.7 cw(c227.05,24.85) 226.9,24.85 226.9,27.35 cw(c227.05,27.35) 227.05,27.5 228.15,27.5 cw(c228.15,27.35) 228.3,27.35 228.3,24.85 cw(c228.15,24.85) 228.15,24.7
SIG007112 on BOTTOM "BOTTOM369" (solid, pour order 190): 228.4,23.35 cw(c228.4,23.5) 228.25,23.5 228.25,24.15 cw(c228.4,24.15) 228.4,24.3 229.338,24.3 cw(c229.338,24.15) 229.444,24.256 229.756,23.944 cw(c229.65,23.838) 229.8,23.838 229.8,23.5 cw(c229.65,23.5) 229.65,23.35
RY_OFF on BOTTOM "BOTTOM368" (solid, pour order 189): 20 vertices, not listed, extent 148.65,22.844 153.2,28.55
PN on BOTTOM "BOTTOM367" (solid, pour order 188): 240.55,20.8 cw(c240.55,20.95) 240.4,20.95 240.4,21.888 cw(c240.55,21.888) 240.444,21.994 241.306,22.856 cw(c241.412,22.75) 241.412,22.9 244.15,22.9 cw(c244.15,22.75) 244.3,22.75 244.3,20.95 cw(c244.15,20.95) 244.15,20.8
PN on BOTTOM "BOTTOM366" (solid, pour order 187): 152.05,23.5 cw(c152.05,23.65) 151.9,23.65 151.9,25.35 cw(c152.05,25.35) 152.05,25.5 153.05,25.5 cw(c153.05,25.35) 153.2,25.35 153.2,24.412 cw(c153.05,24.412) 153.156,24.306 152.394,23.544 cw(c152.288,23.65) 152.288,23.5
SIG007123 on BOTTOM "BOTTOM365" (solid, pour order 186): 28 vertices, not listed, extent 143.735,24.536 146.493,26.472
SIG8 on BOTTOM "BOTTOM364" (solid, pour order 185): 38 vertices, not listed, extent 89.944,64.588 110.845,125.696
FG1 on BOTTOM "BOTTOM363" (solid, pour order 184): 35 vertices, not listed, extent 46.203,60.144 83.571,97
SIG0012 on BOTTOM "BOTTOM362" (solid, pour order 183): 33 vertices, not listed, extent 99.834,44.474 120.613,71.049
SIG00817 on BOTTOM "BOTTOM361" (solid, pour order 182): 28 vertices, not listed, extent 139.001,73.52 142.042,76.68
PN on BOTTOM "BOTTOM360" (solid, pour order 181): 32 vertices, not listed, extent 136.2,70.15 152.75,80.971
SIG00214 on BOTTOM "BOTTOM359" (solid, pour order 180): 25 vertices, not listed, extent 175.669,29.736 176.531,31.069
SIG00227 on BOTTOM "BOTTOM358" (solid, pour order 179): 21 vertices, not listed, extent 175.64,37.792 176.56,40.508
SIG00210 on BOTTOM "BOTTOM357" (solid, pour order 178): 21 vertices, not listed, extent 175.64,33.292 176.56,36.008
SIG00218 on BOTTOM "BOTTOM356" (solid, pour order 177): 17 vertices, not listed, extent 128.942,27.79 132.258,28.71
SIG00232 on BOTTOM "BOTTOM355" (solid, pour order 176): 23 vertices, not listed, extent 125.952,30.4 129.858,31.5
SIG00232 on BOTTOM "BOTTOM354" (solid, pour order 175): 21 vertices, not listed, extent 123.196,30.4 127.048,31.6
SIG8 on BOTTOM "BOTTOM353" (solid, pour order 174): 26 vertices, not listed, extent 125.902,33.394 129.096,34.916
SIG007121 on BOTTOM "BOTTOM352" (solid, pour order 173): 19 vertices, not listed, extent 134.125,38.317 137.362,39.248
SIG007111 on BOTTOM "BOTTOM351" (solid, pour order 172): 21 vertices, not listed, extent 134.125,32.817 137.342,33.737
SIG007122 on BOTTOM "BOTTOM350" (solid, pour order 171): 19 vertices, not listed, extent 134.125,35.517 137.362,36.548
SIG00847 on BOTTOM "BOTTOM349" (solid, pour order 170): 27 vertices, not listed, extent 218.2,36.691 219.275,41.944
PN on BOTTOM "BOTTOM348" (solid, pour order 169): 30 vertices, not listed, extent 216.725,36.692 217.8,41.944
SIG12 on BOTTOM "BOTTOM347" (solid, pour order 168): 30 vertices, not listed, extent 120.85,79.701 156.85,124.95
PN on BOTTOM "BOTTOM346" (solid, pour order 167): 37 vertices, not listed, extent 227.55,28.15 233.1,36.949
PN on BOTTOM "BOTTOM345" (solid, pour order 166): 169.312,70.55 cw(c169.312,70.7) 169.206,70.594 167.444,72.356 cw(c167.55,72.462) 167.4,72.462 167.4,81.15 cw(c167.55,81.15) 167.55,81.3 169.75,81.3 cw(c169.75,81.15) 169.9,81.15 169.9,77.15 173,74.05 182.9,74.05 cw(c182.9,73.9) 183.05,73.9 183.05,70.7 cw(c182.9,70.7) 182.9,70.55
RY_OFF on BOTTOM "BOTTOM344" (solid, pour order 165): 116.1,84.2 cw(c116.1,84.35) 115.95,84.35 115.95,86.3 cw(c116.1,86.3) 116.1,86.45 116.4,86.45 cw(c116.4,86.3) 116.55,86.3 116.55,84.35 cw(c116.4,84.35) 116.4,84.2
SIG0014 on BOTTOM "BOTTOM343" (solid, pour order 164): 113.95,84.2 cw(c113.95,84.35) 113.8,84.35 113.8,86.75 cw(c113.95,86.75) 113.95,86.9 114.05,86.9 cw(c114.05,86.75) 114.2,86.75 114.2,86.2 115.556,84.844 cw(c115.45,84.738) 115.6,84.738 115.6,84.35 cw(c115.45,84.35) 115.45,84.2
VCC12R0_1 on BOTTOM "BOTTOM342" (solid, pour order 163): 29 vertices, not listed, extent 116.501,85.55 117.899,88.46
SIG007110 on BOTTOM "BOTTOM341" (solid, pour order 162): 19 vertices, not listed, extent 245.64,66.092 246.56,69.608
SIG007115 on BOTTOM "BOTTOM340" (solid, pour order 161): 24 vertices, not listed, extent 248.34,63.628 249.26,67.008
PFC_OUT on BOTTOM "BOTTOM339" (solid, pour order 160): 20 vertices, not listed, extent 239.26,63 241.56,67.005
SIG007120 on BOTTOM "BOTTOM338" (solid, pour order 159): 242.941,67.124 cw(c243.401,67.124) 242.968,67.279 243.168,67.839 242.953,68.439 cw(c243.387,68.594) 242.926,68.594 242.926,69.152 cw(c243.387,69.152) 243.846,69.152 243.846,68.594 cw(c243.387,68.594) 243.82,68.439 243.619,67.879 243.834,67.279 cw(c243.401,67.124) 243.861,67.124 243.861,66.546 cw(c243.401,66.546) 242.941,66.546
SIG9 on BOTTOM "BOTTOM337" (solid, pour order 158): 25 vertices, not listed, extent 68.315,43.763 70.085,47.583
SIG10 on BOTTOM "BOTTOM336" (solid, pour order 157): 27 vertices, not listed, extent 68.315,35.217 70.085,39.037
PN on BOTTOM "BOTTOM335" (solid, pour order 156): 111.962,84.2 cw(c111.962,84.35) 111.856,84.244 111.044,85.056 cw(c111.15,85.162) 111,85.162 111,85.788 cw(c111.15,85.788) 111.044,85.894 112.006,86.856 cw(c112.112,86.75) 112.112,86.9 113.25,86.9 cw(c113.25,86.75) 113.4,86.75 113.4,84.35 cw(c113.25,84.35) 113.25,84.2
SIG00818 on BOTTOM "BOTTOM334" (solid, pour order 155): 197.254,69.689 196.089,70.854 195.138,70.522 cw(c195.056,70.758) 194.973,70.994 198.151,72.104 199.352,73.306 cw(c199.459,73.2) 199.459,73.35 199.6,73.35 cw(c199.6,73.2) 199.75,73.2 199.75,73.059 cw(c199.6,73.059) 199.706,72.953 198.504,71.751 197.394,68.573 cw(c197.158,68.656) 196.922,68.738
ACIN on BOTTOM "BOTTOM333" (solid, pour order 154): 25 vertices, not listed, extent 125.496,39.794 129.898,41
SIG007123 on BOTTOM "BOTTOM332" (solid, pour order 153): 20 vertices, not listed, extent 136.425,30.117 140.949,31.037
LGND on BOTTOM "BOTTOM331" (solid, pour order 152): 88 vertices, not listed, extent 282.35,89.15 321.65,116
PFC_OUT on BOTTOM "BOTTOM330" (solid, pour order 151): 126 vertices, not listed, extent 111.75,42.402 242.16,152.62
PN on BOTTOM "BOTTOM329" (solid, pour order 150): 140.7,150.15 cw(c140.7,150.3) 140.55,150.3 140.55,153 cw(c140.7,153) 140.7,153.15 143.1,153.15 cw(c143.1,153) 143.25,153 143.25,150.3 cw(c143.1,150.3) 143.1,150.15
SIG18 on BOTTOM "BOTTOM328" (solid, pour order 149): 21 vertices, not listed, extent 167.363,79.5 175.791,90.15
SIG11 on BOTTOM "BOTTOM327" (solid, pour order 148): 32 vertices, not listed, extent 166.85,79.865 187.723,97.8
PN on BOTTOM "BOTTOM326" (solid, pour order 147): 136.36,79.35 cw(c136.36,79.5) 136.21,79.5 136.21,81.7 cw(c136.36,81.7) 136.36,81.85 138.56,81.85 cw(c138.56,81.7) 138.71,81.7 138.71,79.5 cw(c138.56,79.5) 138.56,79.35
PN on BOTTOM "BOTTOM325" (solid, pour order 146): 167.56,79.35 cw(c167.56,79.5) 167.41,79.5 167.41,81.7 cw(c167.56,81.7) 167.56,81.85 169.76,81.85 cw(c169.76,81.7) 169.91,81.7 169.91,79.5 cw(c169.76,79.5) 169.76,79.35
SIGN266 on BOTTOM "BOTTOM324" (solid, pour order 145): 178.44,79.35 cw(c178.44,79.5) 178.29,79.5 178.29,81.7 cw(c178.44,81.7) 178.44,81.85 180.64,81.85 cw(c180.64,81.7) 180.79,81.7 180.79,79.5 cw(c180.64,79.5) 180.64,79.35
